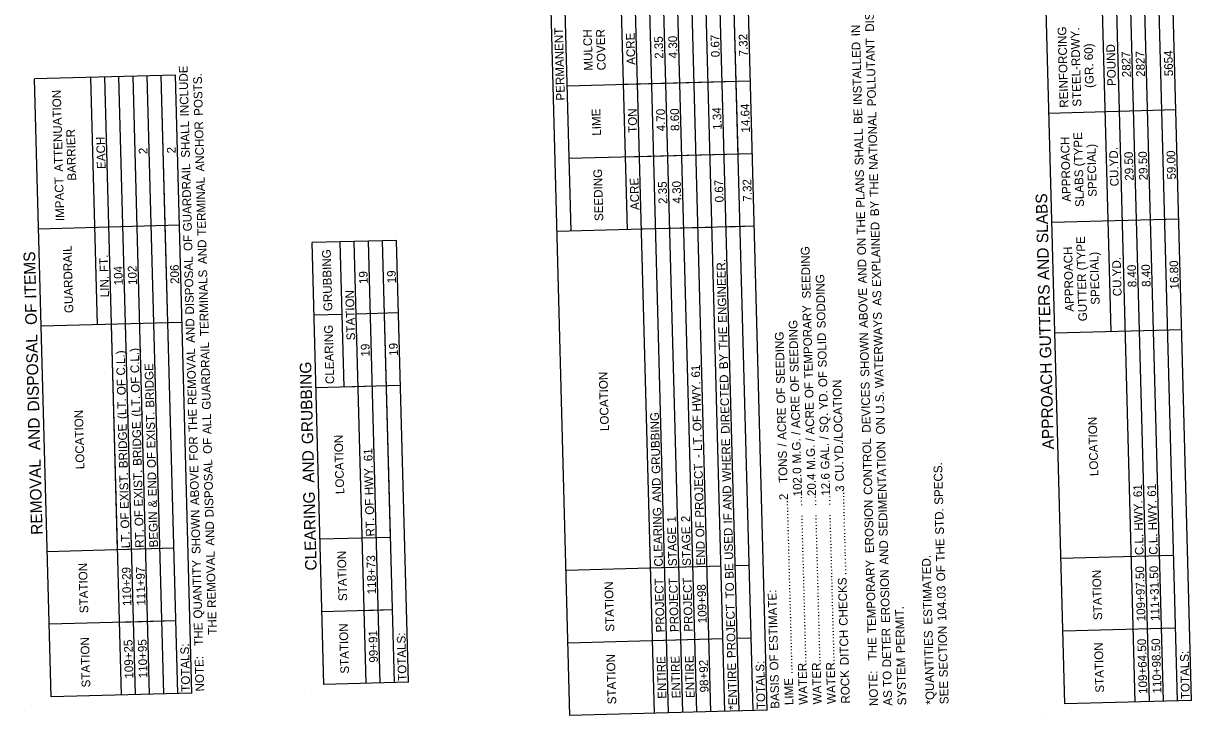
# Model space of a CAD drawing. Extents: x 1930078 to 1931323, y 596452 to 607874.
# Drawn here: x 1930227 to 1931036, y 601457 to 601936 of the extents above; entities that cross this region are included whole.
import ezdxf

# ---------------------------------------------------------------- set-up
doc = ezdxf.new("R2010")
doc.units = 0
doc.layers.add('Default', color=7, linetype='Continuous')
doc.layers.add('R_Border', color=7, linetype='Continuous')

msp = doc.modelspace()

# ---------------------------------------------------------------- linework, layer by layer
at = {"layer": 'Default'}
for p, q in [((1930664.11, 601458.95), (1930632.02, 602654.35)), ((1930673.86, 601459.21), (1930641.77, 602654.62)), ((1930683.6, 601459.47), (1930651.52, 602654.88)), ((1930693.35, 601459.73), (1930661.26, 602655.14)), ((1930703.1, 601459.99), (1930671.01, 602655.4)), ((1930712.84, 601460.26), (1930680.75, 602655.66)), ((1930722.59, 601460.52), (1930690.5, 602655.92)), ((1930742.08, 601461.04), (1930709.99, 602656.45)), ((1930605.63, 601457.38), (1930573.54, 602652.78)), ((1930606.39, 601792.43), (1930583.29, 602653.05)), ((1930645.38, 601793.48), (1930625.66, 602527.88)), ((1930732.34, 601460.78), (1930716.17, 602063.11)), ((1930722, 601845.77), (1930716.17, 602063.11)), ((1930980.11, 601722.94), (1930972.48, 602007.05)), ((1930996.74, 601466.87), (1930982.23, 602007.31)), ((1931006.48, 601467.13), (1930991.97, 602007.57)), ((1931016.23, 601467.39), (1931001.72, 602007.84)), ((1931025.97, 601467.66), (1931011.47, 602008.1)), ((1931025.97, 601467.66), (1931011.47, 602008.1)), ((1931035.72, 601467.92), (1931021.21, 602008.36)), ((1930948, 601465.56), (1930933.5, 602006)), ((1930332.61, 601900.35), (1930235.14, 601897.73)), ((1930246.62, 601470.35), (1930235.14, 601897.73)), ((1930278.72, 601727.73), (1930274.13, 601898.78)), ((1930295.35, 601471.66), (1930283.88, 601899.04)), ((1930305.1, 601471.92), (1930293.62, 601899.3)), ((1930314.84, 601472.18), (1930303.37, 601899.56)), ((1930324.59, 601472.44), (1930313.12, 601899.82)), ((1930334.34, 601472.7), (1930322.86, 601900.09)), ((1930325.65, 601796.29), (1930322.86, 601900.09)), ((1930344.08, 601472.96), (1930332.61, 601900.35)), ((1930730.4, 601896.22), (1930603.7, 601892.82)), ((1930720.66, 601895.96), (1930642.68, 601893.87)), ((1931024.76, 601876.29), (1930937.04, 601873.94)), ((1930731.75, 601846.03), (1930605.04, 601842.63)), ((1930731.75, 601846.03), (1930644.03, 601843.67)), ((1931026.79, 601800.76), (1930939.07, 601798.4)), ((1930335.4, 601796.55), (1930237.93, 601793.93)), ((1930327.45, 601729.04), (1930325.65, 601796.29)), ((1930733.1, 601795.83), (1930596.65, 601792.17)), ((1930703.86, 601795.05), (1930655.12, 601793.74)), ((1930733.1, 601795.83), (1930713.6, 601795.31)), ((1930485.67, 601786.1), (1930427.19, 601784.53)), ((1930446.69, 601785.05), (1930427.19, 601784.53)), ((1930435.4, 601478.97), (1930427.19, 601784.53)), ((1930449.38, 601684.66), (1930446.69, 601785.05)), ((1930475.93, 601785.83), (1930456.43, 601785.31)), ((1930464.64, 601479.76), (1930456.43, 601785.31)), ((1930474.38, 601480.02), (1930466.18, 601785.57)), ((1930484.13, 601480.28), (1930475.93, 601785.83)), ((1930481.43, 601580.67), (1930475.93, 601785.83)), ((1930493.88, 601480.54), (1930485.67, 601786.1)), ((1930448.04, 601734.85), (1930428.54, 601734.33)), ((1930487.02, 601735.9), (1930457.78, 601735.12)), ((1930487.02, 601735.9), (1930457.78, 601735.12)), ((1930337.2, 601729.3), (1930239.74, 601726.68)), ((1930292.65, 601572.05), (1930288.47, 601727.99)), ((1930337.2, 601729.3), (1930327.45, 601729.04)), ((1931028.84, 601724.25), (1930941.12, 601721.89)), ((1930488.37, 601685.71), (1930429.89, 601684.14)), ((1930478.62, 601685.45), (1930449.38, 601684.66)), ((1930481.43, 601580.67), (1930432.7, 601579.36)), ((1930481.43, 601580.67), (1930461.94, 601580.15)), ((1930331.64, 601573.09), (1930243.92, 601570.74)), ((1930331.64, 601573.09), (1930292.65, 601572.05)), ((1931023.28, 601568.04), (1930945.31, 601565.95)), ((1930710.15, 601560.64), (1930602.94, 601557.77)), ((1930710.15, 601560.64), (1930661.42, 601559.34)), ((1930729.64, 601561.17), (1930719.9, 601560.91)), ((1930729.64, 601561.17), (1930719.9, 601560.91)), ((1930482.78, 601530.48), (1930434.05, 601529.17)), ((1930482.78, 601530.48), (1930463.29, 601529.95)), ((1930332.99, 601522.9), (1930245.27, 601520.54)), ((1930332.99, 601522.9), (1930294, 601521.85)), ((1931024.63, 601517.85), (1930946.66, 601515.76)), ((1930711.5, 601510.45), (1930604.29, 601507.57)), ((1930711.5, 601510.45), (1930662.76, 601509.14)), ((1930730.99, 601510.97), (1930721.24, 601510.71)), ((1930730.99, 601510.97), (1930721.24, 601510.71)), ((1930493.88, 601480.54), (1930435.4, 601478.97)), ((1930493.88, 601480.54), (1930435.4, 601478.97)), ((1930344.08, 601472.96), (1930246.62, 601470.35)), ((1930344.08, 601472.96), (1930246.62, 601470.35)), ((1931035.72, 601467.92), (1930948, 601465.56)), ((1930742.08, 601461.04), (1930605.63, 601457.38)), ((1930742.08, 601461.04), (1930605.63, 601457.38))]:
    msp.add_line(p, q, dxfattribs=at)
at = {"layer": 'R_Border'}
for p, q in [((1930421.91, 601472.76), (1930421.91, 601472.76)), ((1930233.13, 601464.13), (1930233.13, 601464.13)), ((1930934.51, 601459.35), (1930934.51, 601459.35))]:
    msp.add_line(p, q, dxfattribs=at)

# ---------------------------------------------------------------- texts
at = {"layer": 'Default'}
for s, height, p in [(' DISCHARGE', 6, (1930816.12, 601928.2)), (' IN', 6, (1930806.45, 601925.08)), ('PERMANENT', 6, (1930602.09, 601882.88)), ('MULCH', 6, (1930621.41, 601903.59)), ('COVER', 6, (1930630.41, 601903.76)), ('ACRE', 6, (1930650.87, 601907.53)), ('2.35', 6, (1930670.26, 601911.73)), ('4.30', 6, (1930680.01, 601912.03)), ('0.67', 6, (1930709.25, 601912.8)), ('7.32', 6, (1930728.74, 601913.35)), ('REINFORCING', 6, (1930950.44, 601877.87)), ('STEEL-RDWY.', 6, (1930959.42, 601878.62)), (' INSTALLED', 6, (1930807.73, 601877.56)), (' POLLUTANT', 6, (1930817.51, 601876.68)), ('(GR. 60)', 6, (1930968.08, 601891.59)), ('POUND', 6, (1930983.42, 601892.92)), ('2827', 6, (1930993.69, 601899)), ('2827', 6, (1931003.43, 601899.26)), ('5654', 6, (1931022.93, 601899.69)), (' INCLUDE', 6, (1930341.99, 601869.68)), (' POSTS.', 6, (1930351.73, 601870.08)), (' ATTENUATION', 6, (1930254.93, 601831.43)), ('1.34', 6, (1930710.6, 601862.62)), ('14.64', 6, (1930730.15, 601860.71)), ('LIME', 6, (1930627.13, 601858.53)), ('TON', 6, (1930652.13, 601860.49)), ('4.70', 6, (1930671.61, 601861.57)), ('8.60', 6, (1930681.36, 601861.83)), (' BE', 6, (1930808.08, 601864.5)), (' NATIONAL', 6, (1930818.69, 601832.74)), ('BARRIER', 6, (1930264.04, 601827.49)), (' SHALL', 6, (1930342.75, 601841.1)), (' ANCHOR', 6, (1930352.76, 601831.55)), (' SHALL', 6, (1930808.85, 601835.91)), ('EACH', 6, (1930284.38, 601835.56)), ('APPROACH', 6, (1930952.18, 601812.87)), ('SLABS (TYPE', 6, (1930961.28, 601809.28)), ('2', 6, (1930313.37, 601845.79)), ('2', 6, (1930332.86, 601846.3)), ('SPECIAL) ', 6, (1930970.1, 601816.3)), ('CU.YD.', 6, (1930985.29, 601823.52)), ('29.50', 6, (1930995.61, 601827.43)), ('29.50', 6, (1931005.36, 601827.69)), ('59.00', 6, (1931024.85, 601828.22)), (' GUARDRAIL', 6, (1930344.12, 601790.18)), ('IMPACT', 6, (1930255.79, 601799.48)), (' TERMINAL', 6, (1930353.95, 601787.15)), ('SEEDING', 6, (1930628.71, 601799.52)), ('ACRE', 6, (1930653.56, 601807.14)), (' PLANS', 6, (1930809.64, 601806.54)), (' THE', 6, (1930819.19, 601814.1)), ('2.35', 6, (1930672.96, 601811.34)), ('4.30', 6, (1930682.7, 601811.64)), ('0.67', 6, (1930711.94, 601812.41)), ('7.32', 6, (1930731.44, 601812.96)), (' BY', 6, (1930819.55, 601800.65)), ('APPROACH GUTTERS AND SLABS', 8, (1930940.45, 601641.61)), (' THE', 6, (1930810.14, 601787.9)), (' EXPLAINED', 6, (1930820.86, 601751.73)), (' OF', 6, (1930344.48, 601776.59)), ('GUTTER (TYPE', 6, (1930963.41, 601730.23)), ('GUARDRAIL', 6, (1930262, 601735.89)), (' AND', 6, (1930354.48, 601767.57)), (' SEEDING', 6, (1930772.31, 601743.73)), (' ON', 6, (1930810.52, 601773.69)), ('APPROACH', 6, (1930954.23, 601736.85)), (' ITEMS', 8, (1930236.48, 601742.84)), (' FT.', 6, (1930286.35, 601762.05)), (' DISPOSAL', 6, (1930345.66, 601732.64)), ('GRUBBING', 6, (1930441.22, 601737.21)), (' ENGINEER.', 6, (1930714.24, 601726.95)), (' AND', 6, (1930811.04, 601754.11)), ('SPECIAL)', 6, (1930972.1, 601741.66)), ('CU.YD.', 6, (1930987.33, 601747.49)), ('104', 6, (1930296.29, 601755.06)), ('102', 6, (1930306.04, 601755.34)), ('206', 6, (1930335.28, 601756.05)), (' TERMINALS', 6, (1930355.82, 601717.72)), ('19', 6, (1930465.78, 601755.97)), ('19', 6, (1930485.27, 601756.5)), ('8.40', 6, (1930997.59, 601753.74)), ('8.40', 6, (1931007.33, 601754)), ('16.80', 6, (1931026.89, 601752.2)), ('LIN.', 6, (1930286.76, 601746.8)), (' SODDING', 6, (1930782.62, 601723.06)), ('STATION', 6, (1930457.07, 601717.03)), (' ABOVE', 6, (1930811.87, 601723.35)), (' AS', 6, (1930821.21, 601738.66)), (' OF', 8, (1930236.96, 601724.73)), (' TEMPORARY', 6, (1930773.79, 601688.37)), (' WATERWAYS', 6, (1930822.74, 601681.82)), (' AND', 6, (1930346.19, 601713.07)), ('CLEARING', 6, (1930442.57, 601686.78)), (' THE', 6, (1930714.74, 601708.3)), (' SEEDING', 6, (1930763.92, 601692.77)), (' DISPOSAL', 8, (1930238.57, 601664.84)), (' SEEDING', 6, (1930754.39, 601684.71)), (' SOLID', 6, (1930783.34, 601696.04)), (' SHOWN', 6, (1930812.78, 601689.58)), (' C.L.)', 6, (1930298.03, 601690.43)), (' C.L.)', 6, (1930307.74, 601692.09)), (' REMOVAL', 6, (1930347.34, 601670.05)), (' GUARDRAIL', 6, (1930357.19, 601666.79)), ('19', 6, (1930467.12, 601705.78)), ('19', 6, (1930486.62, 601706.31)), (' BRIDGE', 6, (1930318.13, 601668.19)), (' GRUBBING', 8, (1930428.19, 601642.26)), (' 61', 6, (1930695.75, 601689.04)), (' BY', 6, (1930715.1, 601694.86)), ('LOCATION', 6, (1930632.61, 601654.29)), (' DIRECTED', 6, (1930716.3, 601650.14)), (' OF', 6, (1930764.29, 601679.19)), (' OF', 6, (1930783.71, 601682.45)), (' OF', 6, (1930298.39, 601676.85)), (' OF', 6, (1930308.1, 601678.51)), (' HWY.', 6, (1930696.38, 601665.57)), (' OF', 6, (1930754.75, 601671.13)), (' OF', 6, (1930774.16, 601674.79)), (' CU.YD./LOCATION', 6, (1930795.21, 601617.22)), (' DEVICES', 6, (1930813.81, 601650.9)), (' (LT.', 6, (1930298.84, 601660.36)), (' (LT.', 6, (1930308.55, 601662.02)), (' ACRE', 6, (1930764.96, 601654.03)), (' YD.', 6, (1930784.12, 601666.89)), (' U.S.', 6, (1930823.22, 601663.93)), ('LOCATION', 6, (1930269.77, 601627.9)), (' THE', 6, (1930347.84, 601651.41)), (' ACRE', 6, (1930755.43, 601645.97)), (' ACRE', 6, (1930774.83, 601649.63)), (' AND', 8, (1930239.29, 601638.08)), (' BRIDGE', 6, (1930309.46, 601628)), (' EXIST.', 6, (1930318.89, 601640.05)), (' ALL', 6, (1930357.64, 601649.85)), (' GRUBBING', 6, (1930668.28, 601622.43)), (' OF', 6, (1930696.74, 601651.99)), (' SQ.', 6, (1930784.56, 601650.86)), (' ON', 6, (1930823.6, 601649.72)), ('LOCATION', 6, (1930971.16, 601623.11)), (' BRIDGE', 6, (1930299.75, 601626.35)), (' LT.', 6, (1930697.11, 601638.29)), (' /', 6, (1930765.09, 601649.37)), (' FOR', 6, (1930348.38, 601631.51)), (' OF', 6, (1930358, 601636.27)), ('LOCATION', 6, (1930449.49, 601610.68)), (' WHERE', 6, (1930717.19, 601617.07)), (' /', 6, (1930755.55, 601641.31)), (' M.G.', 6, (1930765.62, 601629.62)), (' /', 6, (1930774.96, 601644.97)), (' M.G.', 6, (1930775.49, 601625.22)), (' /', 6, (1930784.68, 601646.2)), (' GAL.', 6, (1930785.24, 601625.51)), (' CONTROL', 6, (1930814.97, 601607.9)), (' SEDIMENTATION', 6, (1930825.49, 601579.16)), (' OF', 6, (1930319.25, 601626.47)), (' AND', 8, (1930428.91, 601615.5)), (' 61', 6, (1930469.12, 601631.18)), (' -', 6, (1930697.24, 601633.43)), (' TONS', 6, (1930756.23, 601616.14)), ('REMOVAL', 8, (1930240.78, 601582.54)), (' ABOVE', 6, (1930349.2, 601600.75)), (' DISPOSAL', 6, (1930359.18, 601592.32)), (' HWY.', 6, (1930469.76, 601607.7)), (' PROJECT', 6, (1930698.35, 601592.16)), ('102.0', 6, (1930766.17, 601609.06)), (' SPECS.', 6, (1930863.92, 601601.08)), (' EXIST.', 6, (1930300.51, 601598.21)), (' EXIST.', 6, (1930310.21, 601599.86)), (' END', 6, (1930319.78, 601606.89)), (' AND', 6, (1930668.8, 601602.86)), ('20.4', 6, (1930775.92, 601609.32)), ('12.6', 6, (1930785.66, 601609.58)), ('CLEARING', 8, (1930430.45, 601557.82)), (' AND', 6, (1930717.71, 601597.49)), ('.......3', 6, (1930795.76, 601596.65)), ('C.L. HWY. 61', 6, (1931002.56, 601568.46)), ('C.L. HWY. 61', 6, (1931012.31, 601568.72)), (' &', 6, (1930319.99, 601599.17)), (' OF', 6, (1930470.12, 601594.12)), (' ......................................................2', 6, (1930759.78, 601483.94)), ('…', 6, (1930766.37, 601601.66)), ('…', 6, (1930776.12, 601601.93)), ('…', 6, (1930785.86, 601602.19)), (' EROSION', 6, (1930816.05, 601567.6)), (' OF', 6, (1930300.87, 601584.62)), (' OF', 6, (1930310.58, 601586.28)), ('BEGIN', 6, (1930320.67, 601573.77)), (' SHOWN', 6, (1930350.11, 601566.98)), ('CLEARING', 6, (1930669.94, 601560.54)), (' 1', 6, (1930678.93, 601588.77)), (' 2', 6, (1930688.68, 601589.03)), (' IF', 6, (1930717.97, 601588.1)), (' WATER..............................................', 6, (1930770.1, 601462.77)), (' WATER..............................................', 6, (1930779.84, 601463.03)), (' WATER..............................................', 6, (1930789.59, 601463.29)), ('…', 6, (1930795.96, 601589.26)), (' STD.', 6, (1930864.47, 601580.39)), (' AND', 6, (1930359.71, 601572.75)), ('RT.', 6, (1930470.46, 601581.35)), ('STAGE', 6, (1930679.68, 601560.8)), ('STAGE', 6, (1930689.43, 601561.06)), (' OF', 6, (1930698.71, 601578.57)), (' USED', 6, (1930718.64, 601562.93)), ('…', 6, (1930796.16, 601581.86)), ('LT.', 6, (1930301.18, 601573.25)), ('RT.', 6, (1930310.92, 601573.51)), ('..', 6, (1930796.27, 601577.94)), (' THE', 6, (1930864.98, 601561.75)), (' REMOVAL', 6, (1930360.86, 601529.73)), ('STATION', 6, (1930451.48, 601536.68)), ('END', 6, (1930699.18, 601561.33)), ('…', 6, (1930796.46, 601570.54)), ('.', 6, (1930796.51, 601568.94)), (' AND', 6, (1930826.02, 601559.59)), ('STATION', 6, (1930272.45, 601528.32)), (' QUANTITY', 6, (1930351.31, 601522.34)), ('118+73', 6, (1930471.54, 601541.38)), (' BE', 6, (1930718.99, 601549.87)), ('…', 6, (1930796.71, 601561.55)), (' TEMPORARY', 6, (1930817.54, 601512.25)), (' ESTIMATED.', 6, (1930856.39, 601518.23)), ('110+29', 6, (1930302.25, 601533.27)), ('111+97', 6, (1930311.99, 601533.54)), ('…', 6, (1930796.9, 601554.15)), (' EROSION', 6, (1930827.1, 601519.29)), (' OF', 6, (1930865.34, 601548.17)), ('STATION', 6, (1930973.83, 601523.53)), ('109+97.50', 6, (1931003.79, 601522.68)), ('111+31.50', 6, (1931013.54, 601522.94)), ('STATION', 6, (1930636.33, 601515.48)), ('PROJECT', 6, (1930671.16, 601514.99)), ('PROJECT', 6, (1930680.91, 601515.26)), ('PROJECT', 6, (1930690.65, 601515.52)), ('109+98', 6, (1930700.25, 601521.35)), (' TO', 6, (1930719.36, 601536.28)), (' CHECKS', 6, (1930797.89, 601517.33)), (' 104.03', 6, (1930866.08, 601520.6)), (' ESTIMATE:', 6, (1930749.59, 601500.08)), (' PROJECT', 6, (1930720.46, 601495.01)), (' PERMIT.', 6, (1930837.41, 601498.43)), ('THE', 6, (1930361.3, 601513.42)), ('   THE', 6, (1930351.93, 601499.05)), ('STATION', 6, (1930452.83, 601486.49)), ('99+91', 6, (1930472.8, 601494.09)), ('TOTALS:', 6, (1930492.65, 601481.49)), (' DITCH', 6, (1930798.62, 601490.08)), (' DETER', 6, (1930827.92, 601488.67)), ('*QUANTITIES', 6, (1930857.82, 601465.12)), (' SECTION', 6, (1930867.12, 601481.71)), ('STATION', 6, (1930273.82, 601476.96)), ('109+25', 6, (1930303.6, 601483.06)), ('110+95', 6, (1930313.34, 601483.32)), ('TOTALS:', 6, (1930342.86, 601473.91)), ('   THE', 6, (1930818.16, 601488.95)), ('STATION', 6, (1930975.18, 601473.34)), ('109+64.50', 6, (1931005.14, 601472.48)), ('110+98.50', 6, (1931014.88, 601472.75)), ('NOTE:', 6, (1930352.6, 601474.17)), ('STATION', 6, (1930637.68, 601465.28)), ('ENTIRE', 6, (1930672.39, 601469.13)), ('ENTIRE', 6, (1930682.14, 601469.39)), ('ENTIRE', 6, (1930691.88, 601469.65)), (' OF', 6, (1930749.95, 601486.5)), ('TOTALS:', 6, (1931034.5, 601468.86)), ('98+92', 6, (1930701.53, 601473.52)), ('*ENTIRE', 6, (1930721.36, 601461.46)), ('TOTALS:', 6, (1930740.86, 601461.98)), ('SYSTEM', 6, (1930838.32, 601464.6)), ('BASIS', 6, (1930750.6, 601462.24)), (' LIME', 6, (1930760.35, 601462.51)), (' ROCK', 6, (1930799.34, 601463.55)), ('NOTE:', 6, (1930818.83, 601464.08)), (' TO', 6, (1930828.29, 601475.08)), ('AS', 6, (1930828.58, 601464.34)), ('SEE', 6, (1930867.56, 601465.38))]:
    msp.add_text(s, height=height, rotation=91.53769, dxfattribs=at).set_placement(p)

doc.saveas('drawing.dxf')
